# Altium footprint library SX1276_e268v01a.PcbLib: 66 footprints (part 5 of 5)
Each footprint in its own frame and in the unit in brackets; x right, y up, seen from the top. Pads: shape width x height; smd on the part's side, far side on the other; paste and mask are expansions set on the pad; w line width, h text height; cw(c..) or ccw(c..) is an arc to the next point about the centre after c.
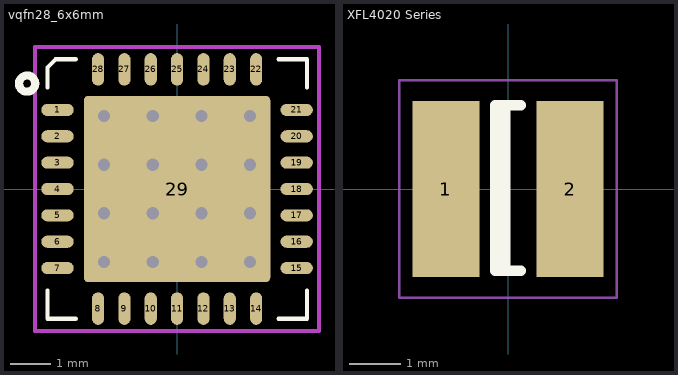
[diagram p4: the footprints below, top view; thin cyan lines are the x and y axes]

## vqfn28_6x6mm [mm] "28 Leads, Body 6.0x6.0mm, Pitch 0.65mm, VQFN28"
height 1
pads (29):
  oval 0.8x0.3 smd mask+0.05: 1(-2.95,1.95) 2(-2.95,1.3) 3(-2.95,0.65) 4(-2.95,0) 5(-2.95,-0.65) 6(-2.95,-1.3) 7(-2.95,-1.95) 15(2.95,-1.95) 16(2.95,-1.3) 17(2.95,-0.65) 18(2.95,0) 19(2.95,0.65) 20(2.95,1.3) 21(2.95,1.95)
  oval 0.3x0.8 smd mask+0.05: 8(-1.95,-2.95) 9(-1.3,-2.95) 10(-0.65,-2.95) 11(0,-2.95) 12(0.65,-2.95) 13(1.3,-2.95) 14(1.95,-2.95) 22(1.95,2.95) 23(1.3,2.95) 24(0.65,2.95) 25(0,2.95) 26(-0.65,2.95) 27(-1.3,2.95) 28(-1.95,2.95)
  rrect5% 4.6x4.6 smd paste-3.3 mask+0.05: 29(0,0)
via 1.8,0.6 diameter 0.6 hole 0.3
via 1.8,1.8 diameter 0.6 hole 0.3
via 0.6,1.8 diameter 0.6 hole 0.3
via 0.6,0.6 diameter 0.6 hole 0.3
via -0.6,-0.6 diameter 0.6 hole 0.3
via -0.6,0.6 diameter 0.6 hole 0.3
via -0.6,1.8 diameter 0.6 hole 0.3
via -1.8,-1.8 diameter 0.6 hole 0.3
via -0.6,-1.8 diameter 0.6 hole 0.3
via 1.8,-1.8 diameter 0.6 hole 0.3
via 0.6,-0.6 diameter 0.6 hole 0.3
via -1.8,0.6 diameter 0.6 hole 0.3
via -1.8,-0.6 diameter 0.6 hole 0.3
via -1.8,1.8 diameter 0.6 hole 0.3
via 1.8,-0.6 diameter 0.6 hole 0.3
via 0.6,-1.8 diameter 0.6 hole 0.3
Top Overlay:
  circle w0.2: c-3.7,2.6 r0.2
  lines w0.1: -3.2,-2.5 -3.2,-3.2 -2.5,-3.2 ; -3.2,2.5 -3.2,3 -3,3.2 -2.5,3.2 ; 2.5,-3.2 3.2,-3.2 3.2,-2.5 ; 2.5,3.2 3.2,3.2 3.2,2.5
Top Paste:
  region: 0.8,1.6 0.8,0.8 1.6,0.8 1.6,1.6
  region: -0.4,0.4 -0.4,-0.4 0.4,-0.4 0.4,0.4
  region: -1.6,0.4 -1.6,-0.4 -0.8,-0.4 -0.8,0.4
  region: -0.4,1.6 -0.4,0.8 0.4,0.8 0.4,1.6
  region: -1.6,1.6 -1.6,0.8 -0.8,0.8 -0.8,1.6
  region: 0.8,0.4 0.8,-0.4 1.6,-0.4 1.6,0.4
  region: -0.4,-0.8 -0.4,-1.6 0.4,-1.6 0.4,-0.8
  region: 0.8,-0.8 0.8,-1.6 1.6,-1.6 1.6,-0.8
  region: -1.6,-0.8 -1.6,-1.6 -0.8,-1.6 -0.8,-0.8
Mechanical 15 keep-out:
  lines w0.1: -3.5,-3.5 3.5,-3.5 3.5,3.5 -3.5,3.5 -3.5,-3.5
3D body: height 1, standoff 0.05, extent -3,-3 3,3

## XFL4020 Series [mm] "Chip SMD component ; Body 4.0 x 4.0 mm (LxW typ)"
height 2.1
pads (2):
  rect 1.3x3.4 smd mask+0.05: 1(-1.2,0) 2(1.2,0)
Top Overlay:
  lines w0.2: -0.056,-1.579 -0.056,1.621 ; 0.25,-1.579 -0.246,-1.579 -0.246,1.621 0.25,1.621
Mechanical 15:
  lines w0.05: -2.1,-2.1 2.1,-2.1 2.1,2.1 -2.1,2.1 -2.1,-2.1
